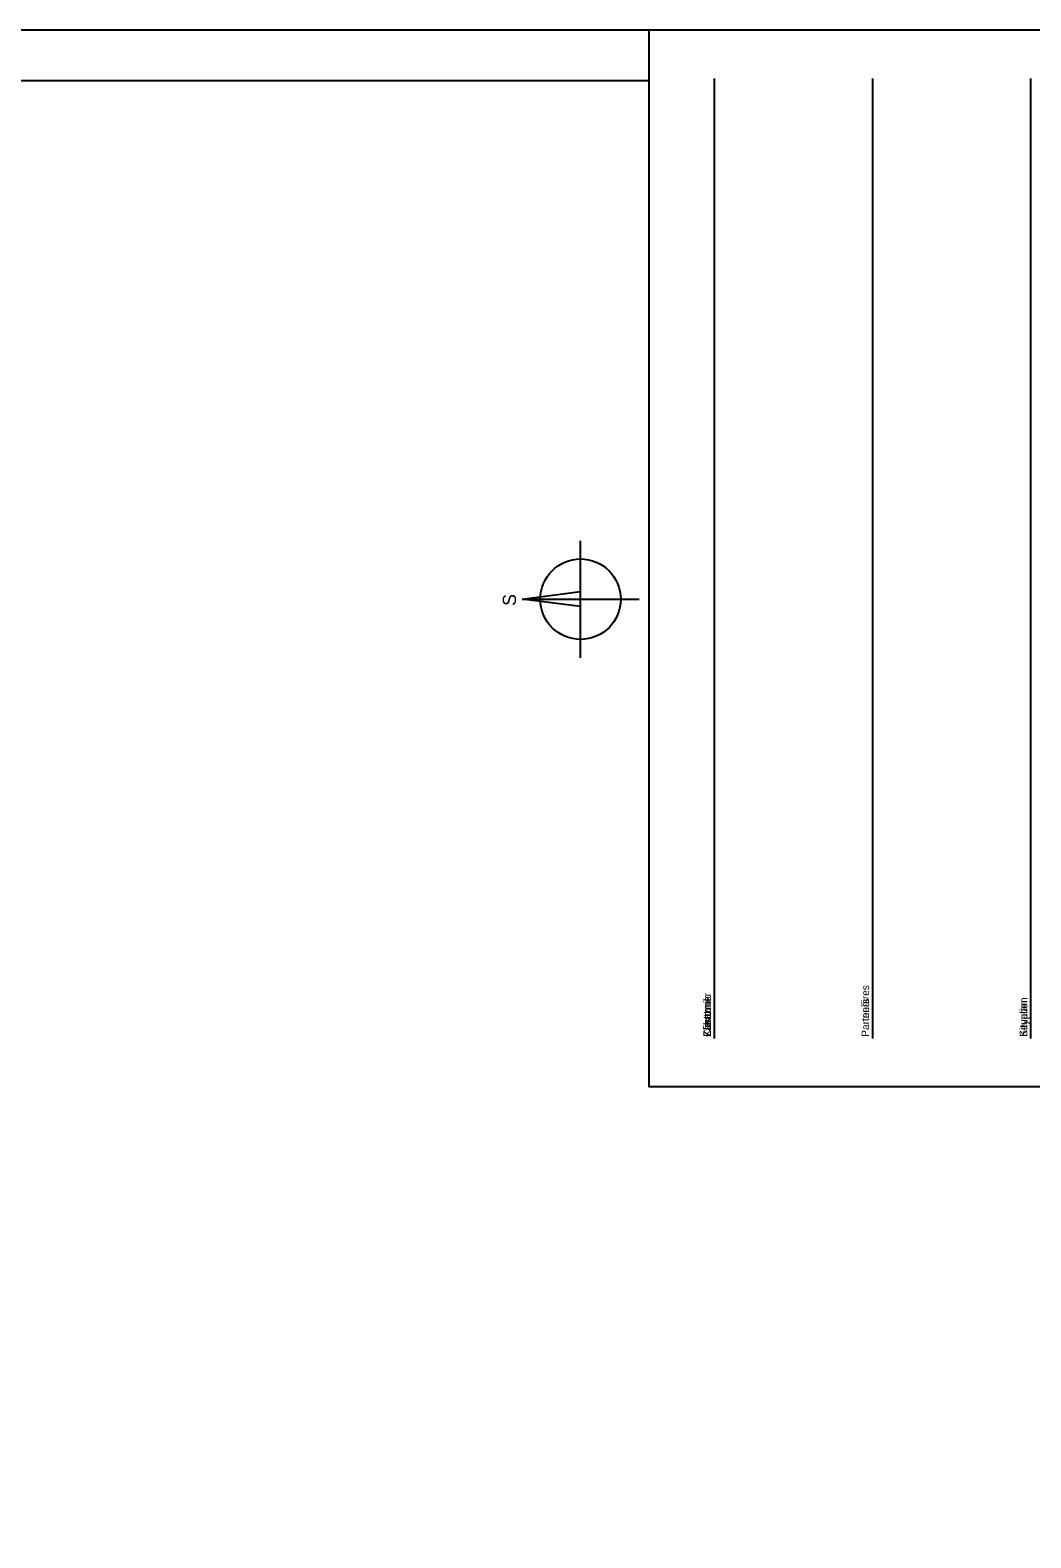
# Model space of a CAD drawing. Extents: x -932963 to -932666, y -737039 to -736000.
# Drawn here: x -932796.7207 to -932796.6213, y -736669.0441 to -736668.8942 of the extents above; entities that cross this region are included whole.
import ezdxf

# ---------------------------------------------------------------- set-up
doc = ezdxf.new("R2010")
doc.units = 0
for name, color, linetype in [('02 BORDER TEXT', 7, 'Continuous'), ('Border', 7, 'Continuous'), ('Border_TextCZ', 7, 'Continuous'), ('Border_TextFR', 7, 'Continuous'), ('Border_TextNL', 7, 'Continuous'), ('Border_TextUK', 7, 'Continuous'), ('Implicitní', 7, 'Continuous')]:
    doc.layers.add(name, color=color, linetype=linetype)

# ---------------------------------------------------------------- blocks, each defined once
blk = doc.blocks.new('SEVER')
at = {"layer": 'Implicitní'}
for p, q in [((-0.148, 0), (0, 1.163)), ((0, 1.163), (0.152, 0)), ((0, 1.163), (0, -1.163)), ((-1.163, 0), (1.163, 0))]:
    blk.add_line(p, q, dxfattribs=at)
blk.add_circle((0, 0), 0.8, dxfattribs=at)
blk.add_text('S', height=0.263, dxfattribs=at).set_placement((-0.132, 1.282))
blk = doc.blocks.new('A0_v03_CZ_1')
at = {"layer": 'Border'}
blk.add_lwpolyline([(0, 0), (1.188, 0), (1.188, 0.84), (0, 0.84)], close=True, dxfattribs=at)
for points in [[(0.978, 0.01), (0.0309, 0.01), (0.0309, 0.8297), (1.178, 0.8297), (1.178, 0.297)], [(0.978, 0), (0.978, 0.297), (1.188, 0.297)], [(0.98758, 0.28402), (1.17842, 0.28402)], [(0.98758, 0.25258), (1.17842, 0.25258)], [(0.98758, 0.22115), (1.17842, 0.22115)]]:
    blk.add_lwpolyline(points, dxfattribs=at)
at = {"layer": 'Border_TextCZ'}
for s, p in [('Zákazník', (0.98794, 0.28473)), ('Partneři', (0.98794, 0.2533)), ('Situace', (0.98794, 0.22187))]:
    blk.add_text(s, height=0.0015, dxfattribs=at).set_placement(p)
at = {"layer": 'Border_TextFR'}
for s, p in [('Client', (0.98794, 0.28473)), ('Partenaires', (0.98794, 0.2533)), ('Situation', (0.98794, 0.22187))]:
    blk.add_text(s, height=0.0015, dxfattribs=at).set_placement(p)
at = {"layer": 'Border_TextNL'}
for s, p in [('Klant', (0.98794, 0.28473)), ('Partners', (0.98794, 0.2533)), ('Situatie', (0.98794, 0.22187))]:
    blk.add_text(s, height=0.0015, dxfattribs=at).set_placement(p)
at = {"layer": 'Border_TextUK'}
for s, p in [('Customer', (0.98794, 0.28473)), ('Partners', (0.98794, 0.2533)), ('Keyplan', (0.98794, 0.22187))]:
    blk.add_text(s, height=0.0015, dxfattribs=at).set_placement(p)

msp = doc.modelspace()

# ---------------------------------------------------------------- block references
at = {"layer": '02 BORDER TEXT', "xscale": 0.004999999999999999, "yscale": 0.005, "rotation": 90.00569318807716}
msp.add_blockref('SEVER', (-932796.66606, -736668.9508), dxfattribs=at)
at = {"layer": 'Border', "xscale": 0.5, "yscale": 0.5, "rotation": 90}
msp.add_blockref('A0_v03_CZ_1', (-932796.51074, -736669.48825), dxfattribs=at)

doc.saveas('drawing.dxf')
